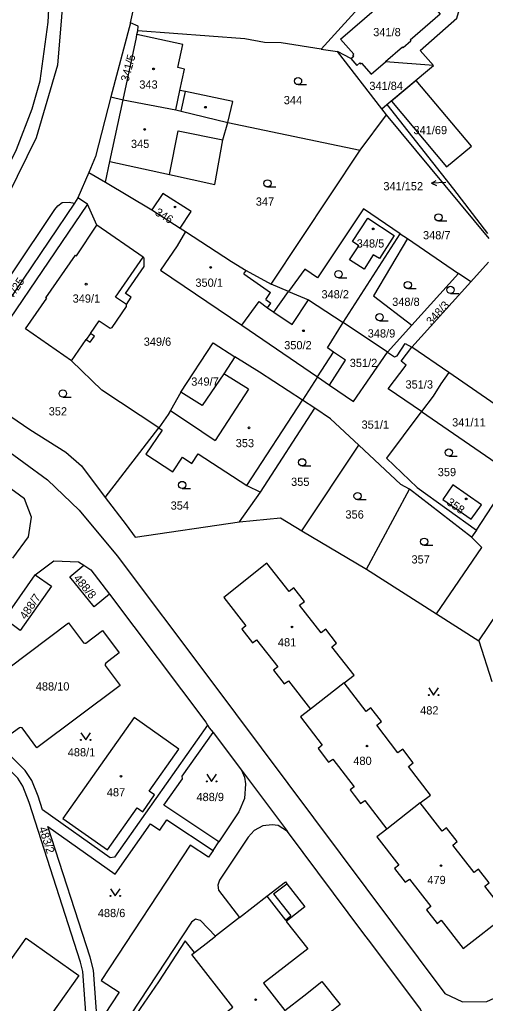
# Model space of a CAD drawing. Extents: x -558500 to -557517, y -1073973 to -1073051.
# Drawn here: x -558006.2 to -557909.9, y -1073436.6 to -1073232.9 of the extents above; entities that cross this region are included whole.
import ezdxf

# ---------------------------------------------------------------- set-up
doc = ezdxf.new("R2010")
doc.units = 0
for name, color, linetype in [('Hranice parcel', 7, 'Continuous'), ('Parcelní čísla', 7, 'Continuous'), ('Pop  PČ popisy', 7, 'Continuous'), ('Svazek obcí údolí Desné', 7, 'Continuous'), ('Vnitřní kresba', 7, 'Continuous'), ('Značky budov', 7, 'Continuous'), ('Značky kultur', 7, 'Continuous')]:
    doc.layers.add(name, color=color, linetype=linetype)

msp = doc.modelspace()

# ---------------------------------------------------------------- linework, layer by layer
at = {"layer": 'Hranice parcel'}
for p, q in [((-557932.67, -1073226.72), (-557943.85, -1073239.02)), ((-557983.29, -1073233.62), (-557987.36, -1073248.89)), ((-557981.96, -1073236.04), (-557981.79, -1073235.24)), ((-557943.85, -1073239.02), (-557940.47, -1073239.54)), ((-557931.28, -1073251.41), (-557940.47, -1073239.54)), ((-557937.69, -1073241), (-557940.47, -1073239.54)), ((-557920.64, -1073242.45), (-557930.56, -1073241.68)), ((-557930.24, -1073250.53), (-557920.64, -1073242.45)), ((-557987.36, -1073248.89), (-557984.8, -1073249.54)), ((-557931.28, -1073251.41), (-557930.24, -1073250.53)), ((-557930.32, -1073252.64), (-557931.28, -1073251.41)), ((-557963.13, -1073254.23), (-557935.78, -1073259.94)), ((-557935.78, -1073259.94), (-557930.32, -1073252.64)), ((-557909.08, -1073278.25), (-557930.32, -1073252.64)), ((-557954.2, -1073287.72), (-557935.78, -1073259.94)), ((-557991.89, -1073264.55), (-557994.13, -1073269.82)), ((-557991.89, -1073264.55), (-557988.45, -1073266.61)), ((-557988.45, -1073266.61), (-557978.88, -1073272.32)), ((-557995.96, -1073270.7), (-557994.86, -1073270.9)), ((-557994.13, -1073269.82), (-557994.86, -1073270.9)), ((-557992.18, -1073271.14), (-557994.13, -1073269.82)), ((-557994.86, -1073270.9), (-558022.09, -1073311.21)), ((-557990.25, -1073275.48), (-557992.18, -1073271.14)), ((-557978.88, -1073272.32), (-557973.02, -1073276.12)), ((-557973.02, -1073276.12), (-557971.93, -1073276.83)), ((-557939.28, -1073295.66), (-557927.49, -1073277.3)), ((-557927.49, -1073277.3), (-557926.01, -1073278.28)), ((-557926.01, -1073278.28), (-557915.41, -1073285.51)), ((-557912.91, -1073287.22), (-557909.23, -1073283.14)), ((-557915.41, -1073285.51), (-557925.06, -1073296.21)), ((-557912.91, -1073287.22), (-557915.41, -1073285.51)), ((-557950.63, -1073289.21), (-557954.2, -1073287.72)), ((-557925.08, -1073300.71), (-557912.91, -1073287.22)), ((-557960.27, -1073296.22), (-557944.6, -1073306.89)), ((-557930.1, -1073301.79), (-557939.28, -1073295.66)), ((-557925.06, -1073296.21), (-557930.1, -1073301.79)), ((-557927.31, -1073303.62), (-557925.08, -1073300.71)), ((-557917.44, -1073306), (-557925.08, -1073300.71)), ((-557944.6, -1073306.89), (-557947.68, -1073311.68)), ((-557944.6, -1073306.89), (-557942.12, -1073308.58)), ((-557923.1, -1073314.09), (-557930, -1073309.35)), ((-557956.39, -1073330.78), (-557945.18, -1073313.34)), ((-557945.18, -1073313.34), (-557947.68, -1073311.68)), ((-557923.1, -1073314.09), (-557906.54, -1073325.46)), ((-557988.49, -1073331.84), (-557977.43, -1073317.43)), ((-557947.81, -1073338.78), (-557936.06, -1073321.05)), ((-557911.75, -1073338.65), (-557904.1, -1073326.9)), ((-557960.73, -1073336.87), (-557956.39, -1073330.78)), ((-557934.44, -1073346.66), (-557925.54, -1073330.14)), ((-557912.73, -1073340.1), (-557925.54, -1073330.14)), ((-557911.2, -1073361.51), (-557892.99, -1073334.25)), ((-557947.81, -1073338.78), (-557934.44, -1073346.66)), ((-557911.75, -1073338.65), (-557912.73, -1073340.1)), ((-558009.3, -1073357), (-558003.01, -1073347.89)), ((-558003.01, -1073347.89), (-557999.59, -1073350.23)), ((-557934.44, -1073346.66), (-557919.99, -1073355.94)), ((-557999.59, -1073350.23), (-558006.08, -1073359.37)), ((-557919.99, -1073355.94), (-557911.2, -1073361.51)), ((-558006.08, -1073359.37), (-558009.3, -1073357)), ((-557911.2, -1073361.51), (-557908.52, -1073369.92)), ((-557939.06, -1073370.25), (-557946.07, -1073375.66)), ((-557967.34, -1073378.97), (-557986.61, -1073406.29)), ((-557972.56, -1073389.56), (-557966.21, -1073380.53)), ((-557966.21, -1073380.53), (-557960.31, -1073388.29)), ((-557960.31, -1073388.29), (-557950.81, -1073400.97)), ((-557960.31, -1073388.29), (-557959.73, -1073389.78)), ((-557923.37, -1073395.09), (-557930.26, -1073400.48)), ((-557950.81, -1073400.97), (-557952.73, -1073399.73)), ((-557966.19, -1073404.96), (-557964.99, -1073403.16)), ((-557965.04, -1073413.14), (-557960.73, -1073418.81)), ((-557965.67, -1073422.67), (-557968.81, -1073419.39)), ((-557960.73, -1073418.81), (-557965.67, -1073422.67)), ((-557970.03, -1073426.04), (-557971.99, -1073423.64))]:
    msp.add_line(p, q, dxfattribs=at)
for points in [[(-557920.64, -1073242.45), (-557923.35, -1073239.36), (-557915.81, -1073232.62), (-557914.61, -1073228.54), (-557915.51, -1073225.19), (-557921.13, -1073218.15), (-557924.3, -1073214.73)], [(-557998.11, -1073217.81), (-557996.7, -1073222.28), (-557998.38, -1073242.39), (-558002.78, -1073257.43), (-558008.62, -1073269.37), (-558024.06, -1073293.44), (-558032.02, -1073303.96), (-558033.31, -1073305.78)], [(-557983.29, -1073233.62), (-557982.1, -1073228.28), (-557983.46, -1073223.81)], [(-557937.69, -1073241), (-557937.08, -1073240.47), (-557937.28, -1073240.24), (-557937.09, -1073240.08), (-557939.85, -1073236.97), (-557925.45, -1073224.49), (-557919.26, -1073231.82), (-557925.44, -1073237.21), (-557925.27, -1073237.41), (-557926.88, -1073238.81), (-557927.05, -1073238.61), (-557930.56, -1073241.68)], [(-557981.79, -1073235.24), (-557981.67, -1073234.3), (-557983.29, -1073233.62)], [(-557984.8, -1073249.54), (-557982.04, -1073236.64), (-557981.96, -1073236.04)], [(-557963.13, -1073254.23), (-557962.1, -1073249.91), (-557971.91, -1073247.83), (-557973.07, -1073247.59), (-557972.12, -1073243.17), (-557973.48, -1073242.88), (-557972.48, -1073238.09), (-557981.96, -1073236.04)], [(-557943.85, -1073239.02), (-557952.12, -1073237.75), (-557955.56, -1073237.67), (-557959.65, -1073236.94), (-557981.79, -1073235.24)], [(-557937.69, -1073241), (-557936.45, -1073242.42), (-557935.84, -1073241.9), (-557935.68, -1073242.09), (-557935.49, -1073241.92), (-557933.49, -1073244.23), (-557930.56, -1073241.68)], [(-557912.73, -1073259.16), (-557924.17, -1073245.52), (-557929.3, -1073249.85), (-557917.91, -1073263.41), (-557912.73, -1073259.16)], [(-557987.36, -1073248.89), (-557990.48, -1073261.24), (-557991.89, -1073264.55)], [(-557984.8, -1073249.54), (-557973.92, -1073251.6), (-557972.79, -1073251.88), (-557963.13, -1073254.23)], [(-557930.24, -1073250.53), (-557916.49, -1073268.06), (-557909.46, -1073277.19)], [(-557988.45, -1073266.61), (-557987.54, -1073262.34), (-557975.19, -1073264.98), (-557965.84, -1073267.06), (-557964.16, -1073257.82), (-557963.13, -1073254.23)], [(-558021.55, -1073305.19), (-558007.79, -1073285.56), (-557998.91, -1073272.25), (-557998.29, -1073271.45), (-557997.41, -1073270.82), (-557995.96, -1073270.7)], [(-557973.02, -1073276.12), (-557970.72, -1073272.68), (-557976.62, -1073268.9), (-557978.88, -1073272.32)], [(-557992.18, -1073271.14), (-558017.7, -1073308.66), (-558015.75, -1073309.85), (-558004.08, -1073317.8), (-557996.67, -1073322.48), (-557993.43, -1073325.31), (-557988.49, -1073331.84)], [(-557927.49, -1073277.3), (-557935.12, -1073272.11), (-557944.58, -1073286.41), (-557947.22, -1073284.58), (-557950.63, -1073289.21)], [(-557937.99, -1073282.67), (-557936.08, -1073279.73), (-557937.34, -1073278.85), (-557934.2, -1073274.07), (-557928.77, -1073277.64), (-557931.8, -1073282.4), (-557933.09, -1073281.6), (-557934.98, -1073284.6), (-557937.99, -1073282.67)], [(-557995.47, -1073303.55), (-558004.99, -1073296.92), (-558000.61, -1073290.62), (-558000.75, -1073290.52), (-557994.62, -1073281.73), (-557994.47, -1073281.84), (-557990.25, -1073275.48)], [(-557995.47, -1073303.55), (-557992.42, -1073299.14), (-557991.6, -1073299.71), (-557990.74, -1073298.46), (-557991.57, -1073297.9), (-557989.74, -1073295.26), (-557987.45, -1073296.82), (-557987.09, -1073296.7), (-557984.08, -1073292.32), (-557984.13, -1073291.92), (-557983.12, -1073290.42), (-557984.28, -1073289.64), (-557980.42, -1073284.02), (-557980.45, -1073282.32), (-557980.68, -1073282.11), (-557990.25, -1073275.48)], [(-557971.93, -1073276.83), (-557973.65, -1073279.73), (-557977.09, -1073284.77), (-557960.27, -1073296.22)], [(-557971.93, -1073276.83), (-557962.4, -1073283.03), (-557959.33, -1073284.84), (-557954.2, -1073287.72)], [(-557926.01, -1073278.28), (-557933.02, -1073290.08), (-557925.06, -1073296.21)], [(-557960.27, -1073296.22), (-557956.66, -1073291.3), (-557954.92, -1073292.62), (-557953.6, -1073293.52), (-557950.63, -1073289.21)], [(-557950.63, -1073289.21), (-557946.45, -1073290.96), (-557939.28, -1073295.66)], [(-557942.12, -1073308.58), (-557938.8, -1073303.44), (-557941.3, -1073301.76), (-557942.56, -1073300.91), (-557939.28, -1073295.66)], [(-557972.83, -1073310.08), (-557966.21, -1073299.85), (-557961.67, -1073302.72)], [(-557930.1, -1073301.79), (-557928.7, -1073302.72), (-557928.1, -1073302.55), (-557926.47, -1073299.96), (-557925.08, -1073300.71)], [(-557961.67, -1073302.72), (-557963.96, -1073306.23), (-557968.46, -1073312.83), (-557972.83, -1073310.08)], [(-557947.68, -1073311.68), (-557956.58, -1073305.91), (-557961.67, -1073302.72)], [(-557942.12, -1073308.58), (-557937.16, -1073311.96), (-557930.1, -1073301.79)], [(-557977.43, -1073317.43), (-557989.2, -1073309.62), (-557995.47, -1073303.55)], [(-557930, -1073309.35), (-557926.23, -1073304.45), (-557927.31, -1073303.62)], [(-557917.44, -1073306), (-557919.08, -1073308.35), (-557920.7, -1073310.88), (-557923.1, -1073314.09)], [(-557906.54, -1073325.46), (-557900.99, -1073317.38), (-557917.44, -1073306)], [(-558022.09, -1073311.21), (-558020.08, -1073313.87), (-558000.41, -1073328.2), (-557993.92, -1073334.5), (-557986.04, -1073343.93), (-557967.1, -1073369.2), (-557918.24, -1073434.51), (-557914.64, -1073436.24), (-557909.55, -1073436.22), (-557905.05, -1073434.1), (-557902.57, -1073430.65), (-557891.22, -1073414.37), (-557877.97, -1073395.43)], [(-557972.83, -1073310.08), (-557975.02, -1073313.87), (-557975.51, -1073314.71), (-557977.43, -1073317.43)], [(-557936.06, -1073321.05), (-557941.93, -1073315.57), (-557945.18, -1073313.34)], [(-557923.1, -1073314.09), (-557923.42, -1073314.47), (-557930.3, -1073323.72), (-557923.97, -1073329.78), (-557911.75, -1073338.65)], [(-557977.43, -1073317.43), (-557976.74, -1073317.89), (-557980.07, -1073322.91)], [(-557925.54, -1073330.14), (-557927.37, -1073329.18), (-557936.06, -1073321.05)], [(-557980.07, -1073322.91), (-557974.55, -1073326.57), (-557972.53, -1073323.54), (-557970.61, -1073324.82)], [(-557970.61, -1073324.82), (-557969.28, -1073322.81), (-557959.2, -1073329.4), (-557956.39, -1073330.78)], [(-558007.59, -1073344.4), (-558004.4, -1073339.98), (-558003.75, -1073335.95), (-558005.22, -1073332.12), (-558012.98, -1073326.49)], [(-557916.62, -1073329.24), (-557918.71, -1073332.26), (-557912.81, -1073336.33), (-557910.69, -1073333.4), (-557916.62, -1073329.24)], [(-557988.49, -1073331.84), (-557984.2, -1073337.5), (-557982.34, -1073340.07), (-557960.73, -1073336.87)], [(-557960.73, -1073336.87), (-557952.24, -1073336.05), (-557947.81, -1073338.78)], [(-557919.99, -1073355.94), (-557910.58, -1073342.2), (-557912.73, -1073340.1)], [(-558003.01, -1073347.89), (-557999.15, -1073344.94), (-557994.02, -1073345.2), (-557992.92, -1073345.89)], [(-557987.64, -1073351.9), (-557990.77, -1073354.47), (-557995.82, -1073348.28), (-557992.92, -1073345.89)], [(-557992.92, -1073345.89), (-557991.47, -1073346.8), (-557987.64, -1073351.9)], [(-557939.06, -1073370.25), (-557937.03, -1073368.65), (-557941.61, -1073362.76), (-557940.64, -1073362.01), (-557942.87, -1073359.14), (-557943.85, -1073359.89), (-557948.29, -1073354.18), (-557947.32, -1073353.42), (-557949.52, -1073350.59), (-557950.49, -1073351.35), (-557955.09, -1073345.44), (-557963.96, -1073352.54), (-557959.4, -1073358.42), (-557960.27, -1073359.1), (-557958.05, -1073361.97), (-557957.18, -1073361.3), (-557952.83, -1073366.91), (-557953.7, -1073367.59), (-557951.48, -1073370.46), (-557950.61, -1073369.79), (-557946.07, -1073375.66)], [(-557987.64, -1073351.9), (-557967.72, -1073378.38), (-557967.34, -1073378.97)], [(-557997.16, -1073446.28), (-557996.18, -1073446.14), (-557992.37, -1073440.37), (-557993.13, -1073429.99), (-557993.58, -1073428.02), (-558004.25, -1073395), (-558005.55, -1073391.58), (-558006.57, -1073389.94), (-558009.69, -1073386.81), (-558015.69, -1073381.13), (-558022.86, -1073375.1), (-558038.38, -1073364.54), (-558051.46, -1073355.75)], [(-558015.07, -1073378.83), (-558009.7, -1073374.87), (-558009.55, -1073374.62), (-558009.63, -1073374.36), (-558012.72, -1073370.26), (-557996.07, -1073357.8), (-557992.97, -1073361.92), (-557992.74, -1073362.04), (-557992.48, -1073361.98), (-557989.05, -1073359.38), (-557985.61, -1073364.04), (-557988.36, -1073366.15), (-557988.52, -1073366.38), (-557988.48, -1073366.66), (-557985.4, -1073370.76), (-558002.63, -1073383.68), (-558005.71, -1073379.56), (-558005.98, -1073379.48), (-558006.26, -1073379.51), (-558009.96, -1073382.24), (-558012.37, -1073378.99), (-558013.71, -1073380.01)], [(-557923.37, -1073395.09), (-557921.26, -1073393.45), (-557925.78, -1073387.56), (-557924.79, -1073386.8), (-557926.98, -1073383.94), (-557927.98, -1073384.7), (-557932.34, -1073379.01), (-557931.35, -1073378.25), (-557933.54, -1073375.39), (-557934.53, -1073376.15), (-557939.06, -1073370.25)], [(-557946.07, -1073375.66), (-557948.14, -1073377.29), (-557943.62, -1073383.15), (-557944.49, -1073383.82), (-557942.29, -1073386.67), (-557941.42, -1073386), (-557937, -1073391.73), (-557937.87, -1073392.4), (-557937.04, -1073393.49), (-557935.69, -1073395.23), (-557934.82, -1073394.56), (-557930.26, -1073400.48)], [(-557973.25, -1073383.95), (-557982.53, -1073377.43), (-557997.25, -1073398.28), (-557988.03, -1073404.82), (-557981.86, -1073396.11), (-557980.74, -1073396.9), (-557978.29, -1073393.44), (-557979.41, -1073392.65), (-557973.25, -1073383.95)], [(-557986.61, -1073406.29), (-557987.5, -1073406.44), (-558001.47, -1073396.48), (-558002.38, -1073393.7), (-558003.7, -1073390.42), (-558005.05, -1073388.34), (-558008.08, -1073385.35), (-558013.71, -1073380.01)], [(-557967.34, -1073378.97), (-557966.98, -1073379.52), (-557966.21, -1073380.53)], [(-557964.99, -1073403.16), (-557976.4, -1073395.54), (-557972.54, -1073390.07), (-557972.56, -1073389.56)], [(-557959.73, -1073389.78), (-557959.52, -1073391.14), (-557959.72, -1073394.15), (-557960.86, -1073396.95), (-557963.76, -1073401.26), (-557964.99, -1073403.16)], [(-557930.26, -1073400.48), (-557932.35, -1073402.1), (-557927.81, -1073407.96), (-557928.68, -1073408.63), (-557926.46, -1073411.51), (-557925.59, -1073410.83), (-557921.19, -1073416.52), (-557922.06, -1073417.2), (-557919.87, -1073420.02), (-557919, -1073419.35), (-557914.46, -1073425.22), (-557905.47, -1073418.2), (-557910.01, -1073412.34), (-557909.08, -1073411.62), (-557911.27, -1073408.79), (-557912.2, -1073409.51), (-557916.62, -1073403.8), (-557915.7, -1073403.08), (-557917.89, -1073400.24), (-557918.82, -1073400.96), (-557923.37, -1073395.09)], [(-557990.11, -1073441.11), (-557990.95, -1073429.72), (-557991.6, -1073426.99), (-558000.34, -1073399.97), (-557986.42, -1073409.86), (-557979.13, -1073399.38), (-557977.23, -1073400.7), (-557975.75, -1073398.59), (-557966.19, -1073404.96)], [(-557952.73, -1073399.73), (-557953.94, -1073399.59), (-557955.93, -1073399.82), (-557957.72, -1073400.8), (-557958.97, -1073402.15), (-557964.89, -1073411.09), (-557965.23, -1073412.1), (-557965.04, -1073413.14)], [(-557943.74, -1073483.99), (-557922.57, -1073454.37), (-557920.54, -1073448.62), (-557920.67, -1073443.5), (-557923.32, -1073437.76), (-557933.57, -1073424.07), (-557935, -1073422.19), (-557950.81, -1073400.97)], [(-557966.19, -1073404.96), (-557967.15, -1073406.3), (-557970.9, -1073403.86), (-557989.34, -1073431.82), (-557985.62, -1073434.28), (-557990.11, -1073441.11)], [(-557960.73, -1073418.81), (-557955.07, -1073414.41), (-557951.22, -1073411.42), (-557950.93, -1073411.8), (-557947.21, -1073416.59), (-557951.08, -1073419.63), (-557946.63, -1073425.3), (-557955.8, -1073432.39), (-557951.37, -1073438.08), (-557947.44, -1073435.04), (-557943.73, -1073432.04), (-557939.89, -1073436.78), (-557943.7, -1073439.86), (-557943.42, -1073440.21), (-557947.29, -1073443.23), (-557962.81, -1073455.3), (-557971.36, -1073444.52), (-557962.13, -1073437.38), (-557970.6, -1073426.47), (-557970.03, -1073426.04)], [(-557968.81, -1073419.39), (-557969.8, -1073419.14), (-557970.66, -1073419.77), (-557992.19, -1073452.45)], [(-558023.22, -1073448.98), (-558004.82, -1073423.06), (-557993.94, -1073430.83), (-558002.36, -1073442.69), (-558001.05, -1073443.62)], [(-557970.03, -1073426.04), (-557967.63, -1073424.2), (-557965.67, -1073422.67)], [(-557971.99, -1073423.64), (-557977.49, -1073432.15), (-557981.25, -1073437.64), (-557989.89, -1073450.63)]]:
    msp.add_lwpolyline(points, dxfattribs=at)
at = {"layer": 'Pop  PČ popisy'}
for p, q in [((-557921.05, -1073266.82), (-557920.07, -1073266.27)), ((-557918.05, -1073266.66), (-557921.05, -1073266.82)), ((-557921.05, -1073266.82), (-557920.02, -1073267.27))]:
    msp.add_line(p, q, dxfattribs=at)
at = {"layer": 'Svazek obcí údolí Desné'}
msp.add_lwpolyline([(-558066.74, -1073350.64), (-558065.9, -1073348.86), (-558061.08, -1073328.44), (-558060.65, -1073327.54), (-558046.7, -1073313.29), (-558030.4, -1073296.27), (-558015.33, -1073274.48), (-558010.02, -1073266.4), (-558006.82, -1073259.79), (-558003.58, -1073251.39), (-558001.93, -1073245.63), (-558000.3, -1073233.47), (-558000.14, -1073230.76), (-558000.21, -1073228.76), (-558000.67, -1073225.31), (-558001.93, -1073222.03), (-558003.18, -1073219.55), (-558003.41, -1073218.32), (-558003.28, -1073217.31), (-558002.8, -1073216.38), (-558000.9, -1073214.81), (-557999.34, -1073213.91), (-558005.3, -1073194.99), (-558007.3, -1073189.81)], dxfattribs=at)
at = {"layer": 'Vnitřní kresba'}
for p, q in [((-557973.92, -1073251.6), (-557973.07, -1073247.59)), ((-557972.79, -1073251.88), (-557971.91, -1073247.83)), ((-557987.54, -1073262.34), (-557984.8, -1073249.54)), ((-557975.19, -1073264.98), (-557973.4, -1073255.98)), ((-557973.4, -1073255.98), (-557964.16, -1073257.82)), ((-557986.39, -1073290.37), (-557980.68, -1073282.11)), ((-557959.81, -1073285.59), (-557959.33, -1073284.84)), ((-557959.81, -1073285.59), (-557954.3, -1073289.39)), ((-557984.13, -1073291.92), (-557986.39, -1073290.37)), ((-557955.3, -1073290.85), (-557954.3, -1073289.39)), ((-557955.3, -1073290.85), (-557954.25, -1073291.61)), ((-557949.87, -1073296.05), (-557946.45, -1073290.96)), ((-557954.92, -1073292.62), (-557954.25, -1073291.61)), ((-557953.6, -1073293.52), (-557949.87, -1073296.05)), ((-557991.57, -1073297.9), (-557992.42, -1073299.14)), ((-557944.6, -1073306.89), (-557941.3, -1073301.76)), ((-557958.88, -1073309.45), (-557963.96, -1073306.23)), ((-557958.88, -1073309.45), (-557965.78, -1073320.06)), ((-557959.2, -1073329.4), (-557947.68, -1073311.68)), ((-557953.7, -1073413.91), (-557950.93, -1073411.8)), ((-557955.07, -1073414.41), (-557951.25, -1073419.34)), ((-557953.7, -1073413.91), (-557950.12, -1073418.46)), ((-557951.25, -1073419.34), (-557950.12, -1073418.46))]:
    msp.add_line(p, q, dxfattribs=at)
msp.add_lwpolyline([(-557975.02, -1073313.87), (-557968.52, -1073318.2), (-557965.78, -1073320.06)], dxfattribs=at)
at = {"layer": 'Značky budov'}
for centre in [(-557978.51, -1073243.13), (-557967.78, -1073251.08), (-557980.34, -1073255.67), (-557974.06, -1073271.72), (-557933.08, -1073276.26), (-557966.69, -1073284.23), (-557992.44, -1073287.7), (-557947.51, -1073297.34), (-557958.76, -1073317.44), (-557913.84, -1073332.14), (-557949.87, -1073358.66), (-557934.36, -1073383.3), (-557985.25, -1073389.56), (-557919.07, -1073408.06), (-557957.4, -1073435.82)]:
    msp.add_circle(centre, 0.175, dxfattribs=at)
at = {"layer": 'Značky kultur'}
for p, q in [((-557948.63, -1073246.4), (-557946.88, -1073246.4)), ((-557954.95, -1073267.58), (-557953.2, -1073267.58)), ((-557919.58, -1073274.62), (-557917.83, -1073274.62)), ((-557940.26, -1073286.37), (-557938.51, -1073286.37)), ((-557925.93, -1073288.63), (-557924.18, -1073288.63)), ((-557917.1, -1073289.64), (-557915.35, -1073289.64)), ((-557931.76, -1073295.29), (-557930.01, -1073295.29)), ((-557997.27, -1073311.09), (-557995.52, -1073311.09)), ((-557917.45, -1073323.31), (-557915.7, -1073323.31)), ((-557947.76, -1073325.33), (-557946.01, -1073325.33)), ((-557972.6, -1073330.02), (-557970.85, -1073330.02)), ((-557936.31, -1073332.3), (-557934.56, -1073332.3)), ((-557922.53, -1073341.76), (-557920.78, -1073341.76))]:
    msp.add_line(p, q, dxfattribs=at)
for points in [[(-557921.59, -1073371.27), (-557920.59, -1073372.77), (-557919.59, -1073371.27)], [(-557993.54, -1073380.54), (-557992.54, -1073382.04), (-557991.54, -1073380.54)], [(-557967.51, -1073389.13), (-557966.51, -1073390.63), (-557965.51, -1073389.13)], [(-557987.43, -1073412.84), (-557986.43, -1073414.34), (-557985.43, -1073412.84)]]:
    msp.add_lwpolyline(points, dxfattribs=at)
for centre, radius in [((-557948.63, -1073245.65), 0.75), ((-557954.95, -1073266.83), 0.75), ((-557919.58, -1073273.87), 0.75), ((-557940.26, -1073285.62), 0.75), ((-557925.93, -1073287.88), 0.75), ((-557917.1, -1073288.89), 0.75), ((-557931.76, -1073294.54), 0.75), ((-557997.27, -1073310.34), 0.75), ((-557917.45, -1073322.56), 0.75), ((-557947.76, -1073324.58), 0.75), ((-557972.6, -1073329.27), 0.75), ((-557936.31, -1073331.55), 0.75), ((-557922.53, -1073341.01), 0.75), ((-557921.59, -1073372.77), 0.1), ((-557919.59, -1073372.77), 0.1), ((-557993.54, -1073382.04), 0.1), ((-557991.54, -1073382.04), 0.1), ((-557967.51, -1073390.63), 0.1), ((-557965.51, -1073390.63), 0.1), ((-557987.43, -1073414.34), 0.1), ((-557985.43, -1073414.34), 0.1)]:
    msp.add_circle(centre, radius, dxfattribs=at)

# ---------------------------------------------------------------- texts
at = {"layer": 'Parcelní čísla'}
for s, p in [('341/8', (-557933.08, -1073236.37)), ('343', (-557981.45, -1073247.22)), ('341/84', (-557933.88, -1073247.5)), ('344', (-557951.57, -1073250.45)), ('341/69', (-557924.75, -1073256.65)), ('345', (-557983.18, -1073259.51)), ('341/152', (-557930.98, -1073268.27)), ('347', (-557957.36, -1073271.45)), ('348/7', (-557922.78, -1073278.41)), ('348/5', (-557936.48, -1073280.12)), ('350/1', (-557969.85, -1073288.24)), ('348/2', (-557943.78, -1073290.64)), ('349/1', (-557995.24, -1073291.52)), ('348/8', (-557929.16, -1073292.2)), ('348/9', (-557934.21, -1073298.74)), ('349/6', (-557980.54, -1073300.45)), ('350/2', (-557951.49, -1073301.18)), ('351/2', (-557937.93, -1073304.85)), ('349/7', (-557970.71, -1073308.71)), ('351/3', (-557926.4, -1073309.3)), ('352', (-558000.19, -1073314.87)), ('341/11', (-557916.76, -1073317.15)), ('351/1', (-557935.49, -1073317.62)), ('353', (-557961.51, -1073321.44)), ('359', (-557919.73, -1073327.44)), ('355', (-557950.06, -1073329.45)), ('354', (-557974.97, -1073334.37)), ('356', (-557938.82, -1073336.22)), ('357', (-557925.16, -1073345.52)), ('481', (-557952.79, -1073362.68)), ('488/10', (-558002.86, -1073371.81)), ('482', (-557923.37, -1073376.77)), ('488/1', (-557996.25, -1073385.45)), ('480', (-557937.19, -1073387.21)), ('487', (-557988.17, -1073393.73)), ('488/9', (-557969.63, -1073394.7)), ('479', (-557921.88, -1073411.88)), ('488/6', (-557990.03, -1073418.72))]:
    msp.add_text(s, height=1.7, dxfattribs=at).set_placement(p)
for s, rotation, p in [('341/5', 75, (-557983.69, -1073245.9)), ('346', 328, (-557978.36, -1073273.25)), ('2847/25', 56, (-558009.7, -1073293.88)), ('348/3', 47, (-557921.06, -1073296.33)), ('358', 325, (-557918.04, -1073333.2)), ('488/8', 310, (-557995.15, -1073348.66)), ('488/7', 56, (-558004.94, -1073357.25)), ('483/2', 288, (-558002.27, -1073400.31))]:
    msp.add_text(s, height=1.7, rotation=rotation, dxfattribs=at).set_placement(p)

doc.saveas('drawing.dxf')
